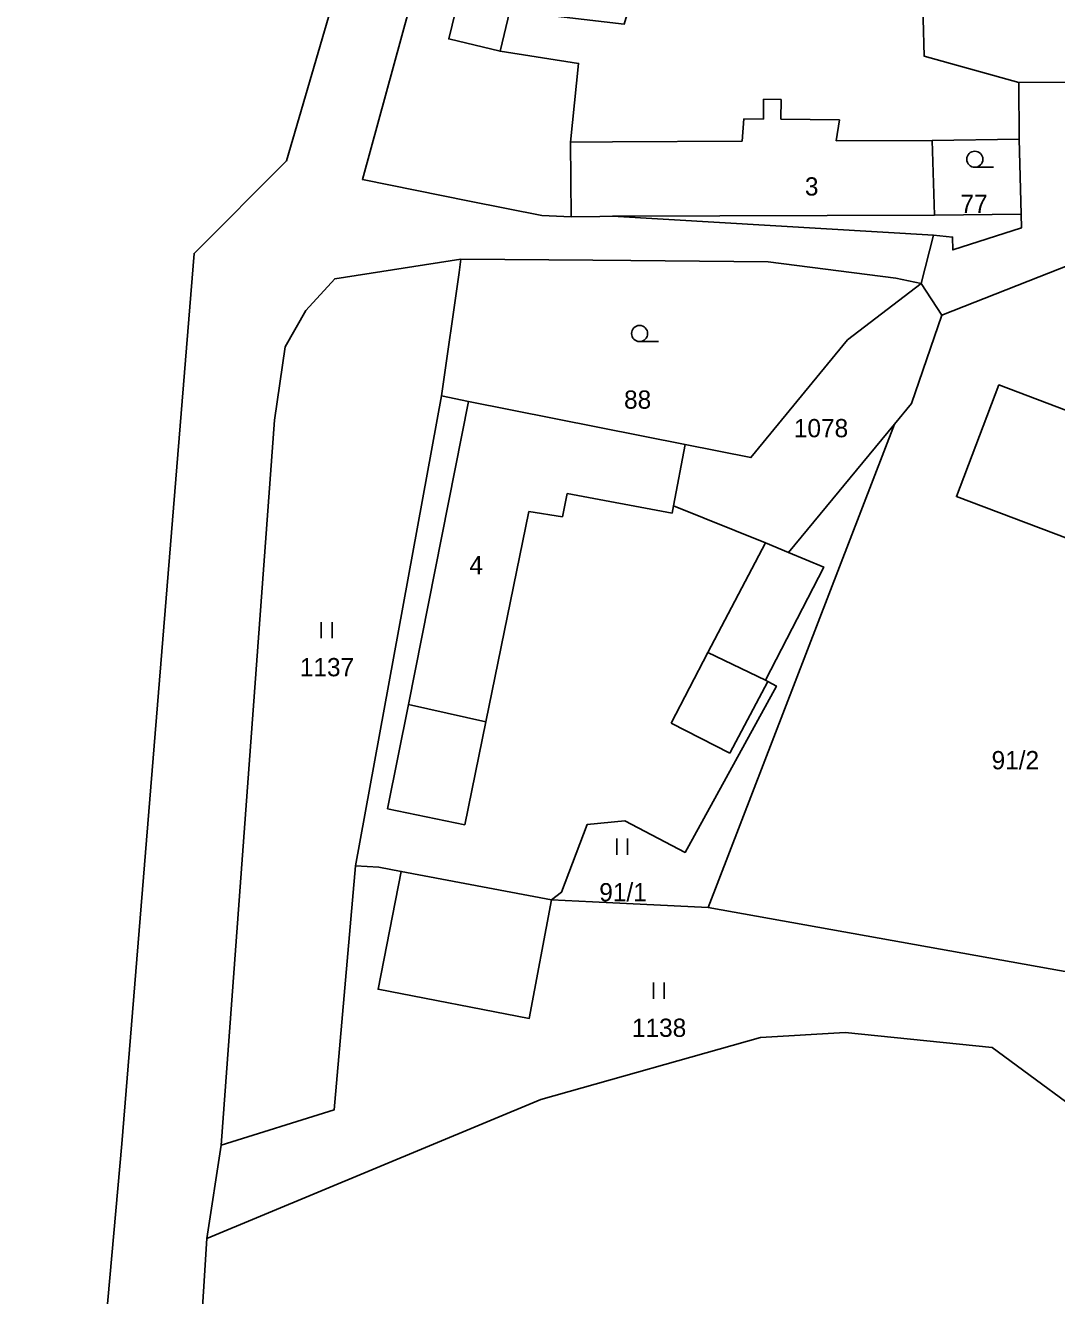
# Model space of a CAD drawing. Extents: x -746176 to -739709, y -1127410 to -1124482.
# Drawn here: x -742472.1 to -742376.1, y -1126206.3 to -1126088.1 of the extents above; entities that cross this region are included whole.
import ezdxf

# ---------------------------------------------------------------- set-up
doc = ezdxf.new("R2010")
doc.units = 0
for name, color, linetype in [('Hranice parcel', 7, 'Continuous'), ('Parcelní čísla', 7, 'Continuous'), ('Vnitřní kresba', 7, 'Continuous'), ('Značky kultur', 7, 'Continuous')]:
    doc.layers.add(name, color=color, linetype=linetype)

msp = doc.modelspace()

# ---------------------------------------------------------------- linework, layer by layer
at = {"layer": 'Hranice parcel'}
for p, q in [((-742379.56, -1126098.64), (-742379.6, -1126093.36)), ((-742379.39, -1126105.64), (-742379.56, -1126098.64)), ((-742387.54, -1126107.59), (-742388.7, -1126112.08)), ((-742386.77, -1126115.04), (-742388.7, -1126112.08)), ((-742389.6, -1126123.26), (-742386.77, -1126115.04)), ((-742433.38, -1126122.54), (-742441.38, -1126166.33)), ((-742391.19, -1126125.19), (-742389.6, -1126123.26)), ((-742408.55, -1126170.19), (-742391.19, -1126125.19)), ((-742391.19, -1126125.19), (-742401.05, -1126137.14)), ((-742408.55, -1126170.19), (-742366.28, -1126177.8)), ((-742455.22, -1126201.03), (-742453.88, -1126192.33))]:
    msp.add_line(p, q, dxfattribs=at)
for points in [[(-742433.87, -1126052.94), (-742447.8, -1126100.68), (-742456.41, -1126109.29), (-742463.16, -1126192.21), (-742472.54, -1126297.27), (-742476.24, -1126360.79), (-742482.39, -1126414.71)], [(-742427.68, -1126054.77), (-742440.74, -1126102.42), (-742430.76, -1126104.41), (-742424.03, -1126105.75), (-742421.29, -1126105.88)], [(-742421.29, -1126105.88), (-742421.35, -1126098.94), (-742420.61, -1126091.6), (-742427.91, -1126090.46), (-742432.7, -1126089.32), (-742431.8, -1126085.57), (-742427.02, -1126086.71), (-742416.37, -1126087.94), (-742414.61, -1126082.07), (-742388.6, -1126083.94), (-742388.43, -1126090.91), (-742379.6, -1126093.36)], [(-742379.6, -1126093.36), (-742370.19, -1126093.35), (-742362.62, -1126088.05), (-742361.35, -1126086.4)], [(-742379.39, -1126105.64), (-742387.46, -1126105.73), (-742387.67, -1126098.78), (-742379.56, -1126098.64)], [(-742387.54, -1126107.59), (-742385.77, -1126107.77), (-742385.76, -1126108.96), (-742379.36, -1126106.92), (-742379.39, -1126105.64)], [(-742421.29, -1126105.88), (-742418.62, -1126105.84), (-742417.46, -1126105.82), (-742387.54, -1126107.59)], [(-742453.88, -1126192.33), (-742448.94, -1126124.82), (-742447.92, -1126117.98), (-742446, -1126114.6), (-742443.31, -1126111.65), (-742431.56, -1126109.81)], [(-742431.56, -1126109.81), (-742431.74, -1126111.07), (-742433.38, -1126122.54)], [(-742388.7, -1126112.08), (-742391.06, -1126111.59), (-742402.96, -1126110.08), (-742415.74, -1126109.96), (-742419.27, -1126109.93), (-742431.56, -1126109.81)], [(-742351.14, -1126116.55), (-742365.05, -1126112.26), (-742373.77, -1126109.92), (-742386.77, -1126115.04)], [(-742388.7, -1126112.08), (-742395.57, -1126117.34), (-742404.55, -1126128.31), (-742410.69, -1126127.09)], [(-742360.61, -1126129.44), (-742370.56, -1126125.67), (-742369.93, -1126124), (-742372.74, -1126122.95), (-742373.37, -1126124.6), (-742381.46, -1126121.54), (-742385.41, -1126131.94), (-742364.54, -1126139.8), (-742360.61, -1126129.44)], [(-742410.69, -1126127.09), (-742430.85, -1126123.08), (-742433.38, -1126122.54)], [(-742410.69, -1126127.09), (-742411.76, -1126132.8), (-742403.21, -1126136.23), (-742401.05, -1126137.14)], [(-742401.05, -1126137.14), (-742397.77, -1126138.5), (-742403.21, -1126149.03), (-742402.98, -1126149.15), (-742402.18, -1126149.59), (-742410.69, -1126165.08), (-742416.29, -1126162.13), (-742419.8, -1126162.46), (-742422.21, -1126168.79), (-742423.12, -1126169.49)], [(-742441.38, -1126166.33), (-742443.37, -1126189.04), (-742453.88, -1126192.33)], [(-742441.38, -1126166.33), (-742439.21, -1126166.45), (-742437.12, -1126166.85), (-742439.28, -1126177.82), (-742425.2, -1126180.54), (-742423.12, -1126169.49)], [(-742423.12, -1126169.49), (-742419.32, -1126169.67), (-742408.55, -1126170.19)], [(-742371.13, -1126191.3), (-742382.1, -1126183.23), (-742395.78, -1126181.85), (-742403.65, -1126182.31), (-742424.12, -1126188.09), (-742455.22, -1126201.03)], [(-742521.95, -1126773.52), (-742504.56, -1126672.68), (-742497, -1126628.23), (-742488.98, -1126567.9), (-742478.35, -1126466.13), (-742467.6, -1126363.23), (-742463.32, -1126296.13), (-742459.73, -1126263.65), (-742452.82, -1126263.88), (-742450.23, -1126260.63), (-742452.38, -1126257.65), (-742458.75, -1126256.81), (-742455.22, -1126201.03)]]:
    msp.add_lwpolyline(points, dxfattribs=at)
at = {"layer": 'Vnitřní kresba'}
for p, q in [((-742427.91, -1126090.46), (-742427.02, -1126086.71)), ((-742403.39, -1126096.78), (-742403.37, -1126094.93)), ((-742403.37, -1126094.93), (-742401.75, -1126094.95)), ((-742401.77, -1126096.8), (-742401.75, -1126094.95)), ((-742405.37, -1126098.85), (-742405.22, -1126096.76)), ((-742405.22, -1126096.76), (-742403.39, -1126096.78)), ((-742401.77, -1126096.8), (-742396.32, -1126096.85)), ((-742396.62, -1126098.81), (-742396.32, -1126096.85)), ((-742421.35, -1126098.94), (-742417.44, -1126098.9)), ((-742417.44, -1126098.9), (-742405.37, -1126098.85)), ((-742396.62, -1126098.81), (-742387.67, -1126098.78)), ((-742417.46, -1126105.82), (-742387.46, -1126105.73)), ((-742436.45, -1126151.3), (-742430.85, -1126123.08)), ((-742422.1, -1126133.81), (-742421.67, -1126131.64)), ((-742421.67, -1126131.64), (-742411.89, -1126133.49)), ((-742411.89, -1126133.49), (-742411.76, -1126132.8)), ((-742429.26, -1126152.92), (-742425.23, -1126133.31)), ((-742425.23, -1126133.31), (-742422.1, -1126133.81)), ((-742408.58, -1126146.46), (-742403.21, -1126136.23)), ((-742408.58, -1126146.46), (-742411.97, -1126153.04)), ((-742408.58, -1126146.46), (-742403.21, -1126149.03)), ((-742406.52, -1126155.83), (-742402.98, -1126149.15)), ((-742436.45, -1126151.3), (-742438.39, -1126161)), ((-742436.45, -1126151.3), (-742429.26, -1126152.92)), ((-742431.21, -1126162.5), (-742429.26, -1126152.92)), ((-742411.97, -1126153.04), (-742406.52, -1126155.83)), ((-742438.39, -1126161), (-742431.21, -1126162.5)), ((-742437.12, -1126166.85), (-742423.12, -1126169.49))]:
    msp.add_line(p, q, dxfattribs=at)
at = {"layer": 'Značky kultur'}
for p, q in [((-742383.703, -1126101.27), (-742381.953, -1126101.27)), ((-742414.923, -1126117.5), (-742413.173, -1126117.5)), ((-742444.571, -1126145.12), (-742444.571, -1126143.62)), ((-742443.57, -1126145.12), (-742443.57, -1126143.62)), ((-742417.041, -1126165.29), (-742417.041, -1126163.79)), ((-742416.04, -1126165.29), (-742416.04, -1126163.79)), ((-742413.641, -1126178.7), (-742413.641, -1126177.2)), ((-742412.64, -1126178.7), (-742412.64, -1126177.2))]:
    msp.add_line(p, q, dxfattribs=at)
for centre in [(-742383.703, -1126100.52), (-742414.923, -1126116.75)]:
    msp.add_circle(centre, 0.75, dxfattribs=at)

# ---------------------------------------------------------------- texts
at = {"layer": 'Parcelní čísla'}
for s, p in [('3', (-742399.53, -1126103.9)), ('77', (-742385.042, -1126105.53)), ('88', (-742416.372, -1126123.75)), ('1078', (-742400.557, -1126126.41)), ('4', (-742430.78, -1126139.17)), ('1137', (-742446.567, -1126148.67)), ('91/2', (-742382.141, -1126157.33)), ('91/1', (-742418.681, -1126169.63)), ('1138', (-742415.637, -1126182.25))]:
    msp.add_text(s, height=1.7, dxfattribs=at).set_placement(p)

doc.saveas('drawing.dxf')
